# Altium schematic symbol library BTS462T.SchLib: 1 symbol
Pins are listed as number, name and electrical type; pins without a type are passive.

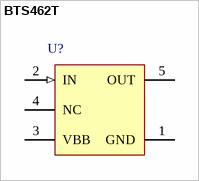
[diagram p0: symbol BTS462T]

## BTS462T
designator U?
Smart High-Side Power Switch, 1 Channel, 4.4 A Load Current, -40 to 150 degC, PG-TO252-5-11, Reel, Green; Manufacturer: Infineon; PartNumber: BTS462T; Channels: 1; Green: TRUE; Group: Automotive Qualified; Load Current (typ): 4.4 A; Ptot (max): 41.6 W; Recommended Operating Voltage Max.: 34 V; Recommended Operating Voltage Min.: 5 V; RON @ 25degreesC: 100 mOhm; RON(max) @ 150degreesC: 200 mOhm; toff (max): 230 us; ton (max): 170 us
footprint INF-PG-TO252-5-11_N (DPAK, 5-Leads, Body 6.5x6.12mm, Pitch 1.14mm, IPC Medium Density)
footprint INF-PG-TO252-5-11_L (DPAK, 5-Leads, Body 6.5x6.12mm, Pitch 1.14mm, IPC High Density)
footprint INF-PG-TO252-5-11_M (DPAK, 5-Leads, Body 6.5x6.12mm, Pitch 1.14mm, IPC Low Density)
pins: 1 GND (power) "Logic ground.", 2 IN (in) "Input, activates the power switch in case of logical high signal.", 3 VBB (power) "Positive power supply voltage.", 4 NC "Not connected.", 5 OUT (power) "Output to the load."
